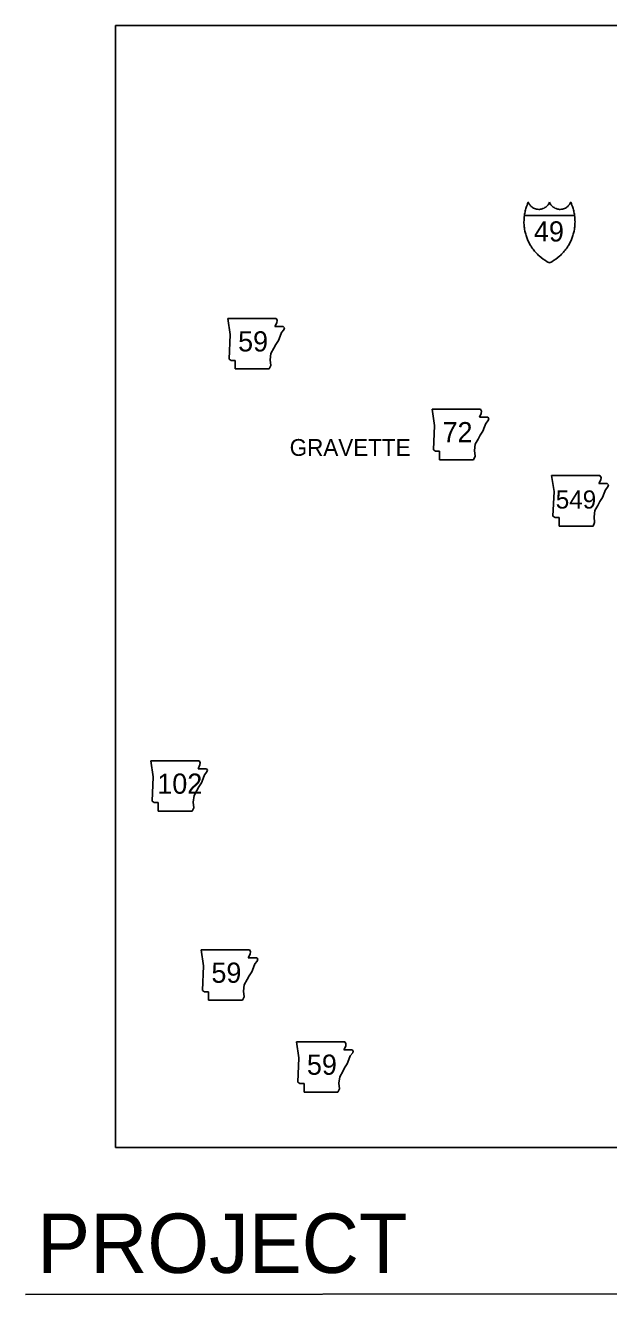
# Model space of a CAD drawing. Extents: x 6028647 to 6035072, y 5366486 to 5368495.
# Drawn here: x 6028660 to 6028935, y 5367847 to 5368445 of the extents above; entities that cross this region are included whole.
import ezdxf

# ---------------------------------------------------------------- set-up
doc = ezdxf.new("R2010")
doc.units = 0
for name, color, linetype in [('21', 7, 'Continuous'), ('22', 7, 'Continuous'), ('23', 7, 'Continuous'), ('25', 7, 'Continuous'), ('Default', 7, 'Continuous'), ('R_NoPlot', 7, 'Continuous')]:
    doc.layers.add(name, color=color, linetype=linetype)

msp = doc.modelspace()

# ---------------------------------------------------------------- linework, layer by layer
at = {"layer": '21'}
for p, q in [((6028755.11, 5368307.3), (6028756.25, 5368299.69)), ((6028777.44, 5368303.5), (6028778.33, 5368305.27)), ((6028778.45, 5368306.41), (6028777.93, 5368307.29)), ((6028778.33, 5368305.27), (6028778.45, 5368306.41)), ((6028756.25, 5368299.69), (6028755.74, 5368288.14)), ((6028781.37, 5368303.5), (6028777.44, 5368303.5)), ((6028779.85, 5368298.93), (6028780.48, 5368300.58)), ((6028780.48, 5368300.58), (6028781.63, 5368301.97)), ((6028781.88, 5368302.86), (6028781.37, 5368303.5)), ((6028781.63, 5368301.97), (6028781.88, 5368302.86)), ((6028775.54, 5368290.81), (6028776.93, 5368293.22)), ((6028776.93, 5368293.22), (6028777.82, 5368294.99)), ((6028777.82, 5368294.99), (6028779.09, 5368296.9)), ((6028779.09, 5368296.9), (6028779.85, 5368298.93)), ((6028755.74, 5368288.14), (6028756.76, 5368287.51)), ((6028756.76, 5368287.51), (6028758.66, 5368287.51)), ((6028758.66, 5368287.51), (6028758.66, 5368283.45)), ((6028775.16, 5368287.76), (6028775.54, 5368290.81)), ((6028775.41, 5368285.1), (6028775.16, 5368287.76)), ((6028758.66, 5368283.45), (6028774.65, 5368283.45)), ((6028774.65, 5368283.45), (6028775.41, 5368285.1)), ((6028851.55, 5368264.49), (6028852.69, 5368256.87)), ((6028874.9, 5368263.6), (6028874.37, 5368264.48)), ((6028874.77, 5368262.46), (6028874.9, 5368263.6)), ((6028873.88, 5368260.68), (6028874.77, 5368262.46)), ((6028877.82, 5368260.68), (6028873.88, 5368260.68)), ((6028876.29, 5368256.11), (6028876.93, 5368257.76)), ((6028876.93, 5368257.76), (6028878.07, 5368259.16)), ((6028878.32, 5368260.05), (6028877.82, 5368260.68)), ((6028878.07, 5368259.16), (6028878.32, 5368260.05)), ((6028852.69, 5368256.87), (6028852.18, 5368245.33)), ((6028873.37, 5368250.4), (6028874.26, 5368252.18)), ((6028874.26, 5368252.18), (6028875.53, 5368254.08)), ((6028875.53, 5368254.08), (6028876.29, 5368256.11)), ((6028852.18, 5368245.33), (6028853.2, 5368244.69)), ((6028871.6, 5368244.95), (6028871.98, 5368247.99)), ((6028871.98, 5368247.99), (6028873.37, 5368250.4)), ((6028853.2, 5368244.69), (6028855.1, 5368244.69)), ((6028855.1, 5368244.69), (6028855.1, 5368240.63)), ((6028855.1, 5368240.63), (6028871.09, 5368240.63)), ((6028871.09, 5368240.63), (6028871.85, 5368242.28)), ((6028871.85, 5368242.28), (6028871.6, 5368244.95)), ((6028907.98, 5368233.21), (6028909.13, 5368225.59)), ((6028930.32, 5368229.4), (6028931.2, 5368231.18)), ((6028934.25, 5368229.4), (6028930.32, 5368229.4)), ((6028931.33, 5368232.32), (6028930.8, 5368233.2)), ((6028931.2, 5368231.18), (6028931.33, 5368232.32)), ((6028933.36, 5368226.48), (6028934.5, 5368227.88)), ((6028934.76, 5368228.77), (6028934.25, 5368229.4)), ((6028934.5, 5368227.88), (6028934.76, 5368228.77)), ((6028909.13, 5368225.59), (6028908.62, 5368214.05)), ((6028930.7, 5368220.9), (6028931.96, 5368222.8)), ((6028931.96, 5368222.8), (6028932.73, 5368224.83)), ((6028932.73, 5368224.83), (6028933.36, 5368226.48)), ((6028928.03, 5368213.67), (6028928.41, 5368216.71)), ((6028928.41, 5368216.71), (6028929.81, 5368219.12)), ((6028929.81, 5368219.12), (6028930.7, 5368220.9)), ((6028908.62, 5368214.05), (6028909.63, 5368213.41)), ((6028909.63, 5368213.41), (6028911.54, 5368213.41)), ((6028911.54, 5368213.41), (6028911.54, 5368209.35)), ((6028911.54, 5368209.35), (6028927.52, 5368209.35)), ((6028927.52, 5368209.35), (6028928.29, 5368211)), ((6028928.29, 5368211), (6028928.03, 5368213.67)), ((6028718.8, 5368098.73), (6028719.94, 5368091.11)), ((6028741.13, 5368094.92), (6028742.01, 5368096.7)), ((6028742.14, 5368097.84), (6028741.62, 5368098.72)), ((6028742.01, 5368096.7), (6028742.14, 5368097.84)), ((6028719.94, 5368091.11), (6028719.43, 5368079.57)), ((6028745.06, 5368094.92), (6028741.13, 5368094.92)), ((6028742.78, 5368088.32), (6028743.54, 5368090.35)), ((6028743.54, 5368090.35), (6028744.17, 5368092)), ((6028744.17, 5368092), (6028745.31, 5368093.4)), ((6028745.57, 5368094.29), (6028745.06, 5368094.92)), ((6028745.31, 5368093.4), (6028745.57, 5368094.29)), ((6028739.22, 5368082.23), (6028740.62, 5368084.64)), ((6028740.62, 5368084.64), (6028741.51, 5368086.42)), ((6028741.51, 5368086.42), (6028742.78, 5368088.32)), ((6028719.43, 5368079.57), (6028720.44, 5368078.93)), ((6028720.44, 5368078.93), (6028722.35, 5368078.93)), ((6028722.35, 5368078.93), (6028722.35, 5368074.87)), ((6028738.84, 5368079.19), (6028739.22, 5368082.23)), ((6028739.1, 5368076.52), (6028738.84, 5368079.19)), ((6028722.35, 5368074.87), (6028738.34, 5368074.87)), ((6028738.34, 5368074.87), (6028739.1, 5368076.52)), ((6028742.52, 5368009.58), (6028743.66, 5368001.97)), ((6028764.85, 5368005.78), (6028765.74, 5368007.55)), ((6028765.87, 5368008.7), (6028765.34, 5368009.57)), ((6028765.74, 5368007.55), (6028765.87, 5368008.7)), ((6028743.66, 5368001.97), (6028743.16, 5367990.42)), ((6028768.79, 5368005.78), (6028764.85, 5368005.78)), ((6028766.5, 5367999.18), (6028767.26, 5368001.21)), ((6028767.26, 5368001.21), (6028767.9, 5368002.86)), ((6028767.9, 5368002.86), (6028769.04, 5368004.25)), ((6028769.29, 5368005.14), (6028768.79, 5368005.78)), ((6028769.04, 5368004.25), (6028769.29, 5368005.14)), ((6028762.95, 5367993.09), (6028764.35, 5367995.5)), ((6028764.35, 5367995.5), (6028765.23, 5367997.28)), ((6028765.23, 5367997.28), (6028766.5, 5367999.18)), ((6028743.16, 5367990.42), (6028744.17, 5367989.79)), ((6028744.17, 5367989.79), (6028746.07, 5367989.79)), ((6028746.07, 5367989.79), (6028746.07, 5367985.73)), ((6028762.57, 5367990.04), (6028762.95, 5367993.09)), ((6028762.82, 5367987.38), (6028762.57, 5367990.04)), ((6028746.07, 5367985.73), (6028762.06, 5367985.73)), ((6028762.06, 5367985.73), (6028762.82, 5367987.38)), ((6028787.58, 5367966.2), (6028788.72, 5367958.59)), ((6028809.91, 5367962.39), (6028810.8, 5367964.17)), ((6028810.93, 5367965.31), (6028810.4, 5367966.19)), ((6028810.8, 5367964.17), (6028810.93, 5367965.31)), ((6028788.72, 5367958.59), (6028788.21, 5367947.04)), ((6028813.84, 5367962.39), (6028809.91, 5367962.39)), ((6028812.32, 5367957.82), (6028812.96, 5367959.47)), ((6028812.96, 5367959.47), (6028814.1, 5367960.87)), ((6028814.35, 5367961.76), (6028813.84, 5367962.39)), ((6028814.1, 5367960.87), (6028814.35, 5367961.76)), ((6028808.01, 5367949.7), (6028809.4, 5367952.11)), ((6028809.4, 5367952.11), (6028810.29, 5367953.89)), ((6028810.29, 5367953.89), (6028811.56, 5367955.79)), ((6028811.56, 5367955.79), (6028812.32, 5367957.82)), ((6028788.21, 5367947.04), (6028789.23, 5367946.41)), ((6028789.23, 5367946.41), (6028791.13, 5367946.41)), ((6028791.13, 5367946.41), (6028791.13, 5367942.34)), ((6028807.63, 5367946.66), (6028808.01, 5367949.7)), ((6028807.88, 5367943.99), (6028807.63, 5367946.66)), ((6028791.13, 5367942.34), (6028807.12, 5367942.34)), ((6028807.12, 5367942.34), (6028807.88, 5367943.99))]:
    msp.add_line(p, q, dxfattribs=at)
for points in [[(6028755.11, 5368307.3), (6028777.93, 5368307.29)], [(6028851.55, 5368264.49), (6028874.37, 5368264.48)], [(6028907.98, 5368233.21), (6028930.8, 5368233.2)], [(6028718.8, 5368098.73), (6028741.62, 5368098.72)], [(6028742.52, 5368009.58), (6028765.34, 5368009.57)], [(6028787.58, 5367966.2), (6028810.4, 5367966.19)]]:
    msp.add_lwpolyline(points, dxfattribs=at)
at = {"layer": '23'}
for points in [[(6028895.15, 5368355.87), (6028895.24, 5368356.44), (6028895.33, 5368356.94), (6028895.46, 5368357.58), (6028895.55, 5368358), (6028895.68, 5368358.5), (6028895.85, 5368359.09), (6028896, 5368359.58), (6028896.17, 5368360.08), (6028896.39, 5368360.71), (6028896.62, 5368361.29), (6028896.82, 5368361.74), (6028896.98, 5368362.1), (6028897.15, 5368361.71), (6028897.35, 5368361.35), (6028897.57, 5368361.01), (6028897.86, 5368360.64), (6028898.09, 5368360.39), (6028898.37, 5368360.11), (6028898.66, 5368359.87), (6028898.96, 5368359.65), (6028899.45, 5368359.36), (6028899.96, 5368359.12), (6028900.41, 5368358.96), (6028900.86, 5368358.84), (6028901.35, 5368358.76), (6028901.91, 5368358.73), (6028902.28, 5368358.73), (6028902.7, 5368358.77), (6028903.08, 5368358.84), (6028903.48, 5368358.94), (6028903.89, 5368359.07), (6028904.44, 5368359.31), (6028904.81, 5368359.53), (6028905.25, 5368359.83), (6028905.67, 5368360.18), (6028905.98, 5368360.49), (6028906.33, 5368360.91), (6028906.62, 5368361.35), (6028906.79, 5368361.65), (6028906.98, 5368362.05)], [(6028895.15, 5368355.87), (6028895.24, 5368356.44), (6028895.33, 5368356.94), (6028895.46, 5368357.58), (6028895.55, 5368358), (6028895.68, 5368358.5), (6028895.85, 5368359.09), (6028896, 5368359.58), (6028896.17, 5368360.08), (6028896.39, 5368360.71), (6028896.62, 5368361.29), (6028896.82, 5368361.74), (6028896.98, 5368362.1), (6028897.15, 5368361.71), (6028897.35, 5368361.35), (6028897.57, 5368361.01), (6028897.86, 5368360.64), (6028898.09, 5368360.39), (6028898.37, 5368360.11), (6028898.66, 5368359.87), (6028898.96, 5368359.65), (6028899.45, 5368359.36), (6028899.96, 5368359.12), (6028900.41, 5368358.96), (6028900.86, 5368358.84), (6028901.35, 5368358.76), (6028901.91, 5368358.73), (6028902.28, 5368358.73), (6028902.7, 5368358.77), (6028903.08, 5368358.84), (6028903.48, 5368358.94), (6028903.89, 5368359.07), (6028904.44, 5368359.31), (6028904.81, 5368359.53), (6028905.25, 5368359.83), (6028905.67, 5368360.18), (6028905.98, 5368360.49), (6028906.33, 5368360.91), (6028906.62, 5368361.35), (6028906.79, 5368361.65), (6028906.98, 5368362.05)], [(6028906.98, 5368362.05), (6028907.16, 5368361.65), (6028907.33, 5368361.35), (6028907.62, 5368360.91), (6028907.97, 5368360.49), (6028908.28, 5368360.18), (6028908.7, 5368359.83), (6028909.14, 5368359.53), (6028909.52, 5368359.31), (6028910.06, 5368359.07), (6028910.47, 5368358.94), (6028910.87, 5368358.84), (6028911.25, 5368358.77), (6028911.68, 5368358.73), (6028912.04, 5368358.73), (6028912.61, 5368358.76), (6028913.09, 5368358.84), (6028913.54, 5368358.96), (6028914, 5368359.12), (6028914.5, 5368359.36), (6028914.99, 5368359.65), (6028915.3, 5368359.87), (6028915.58, 5368360.11), (6028915.86, 5368360.39), (6028916.09, 5368360.64), (6028916.38, 5368361.01), (6028916.6, 5368361.35), (6028916.8, 5368361.71), (6028916.98, 5368362.1), (6028917.14, 5368361.74), (6028917.33, 5368361.29), (6028917.56, 5368360.71), (6028917.79, 5368360.08), (6028917.96, 5368359.58), (6028918.11, 5368359.09), (6028918.27, 5368358.5), (6028918.4, 5368358), (6028918.5, 5368357.58), (6028918.63, 5368356.94), (6028918.72, 5368356.44), (6028918.8, 5368355.87)], [(6028906.98, 5368362.05), (6028907.16, 5368361.65), (6028907.33, 5368361.35), (6028907.62, 5368360.91), (6028907.97, 5368360.49), (6028908.28, 5368360.18), (6028908.7, 5368359.83), (6028909.14, 5368359.53), (6028909.52, 5368359.31), (6028910.06, 5368359.07), (6028910.47, 5368358.94), (6028910.87, 5368358.84), (6028911.25, 5368358.77), (6028911.68, 5368358.73), (6028912.04, 5368358.73), (6028912.61, 5368358.76), (6028913.09, 5368358.84), (6028913.54, 5368358.96), (6028914, 5368359.12), (6028914.5, 5368359.36), (6028914.99, 5368359.65), (6028915.3, 5368359.87), (6028915.58, 5368360.11), (6028915.86, 5368360.39), (6028916.09, 5368360.64), (6028916.38, 5368361.01), (6028916.6, 5368361.35), (6028916.8, 5368361.71), (6028916.98, 5368362.1), (6028917.14, 5368361.74), (6028917.33, 5368361.29), (6028917.56, 5368360.71), (6028917.79, 5368360.08), (6028917.96, 5368359.58), (6028918.11, 5368359.09), (6028918.27, 5368358.5), (6028918.4, 5368358), (6028918.5, 5368357.58), (6028918.63, 5368356.94), (6028918.72, 5368356.44), (6028918.8, 5368355.87)], [(6028906.98, 5368333.47), (6028905.94, 5368334.02), (6028905.03, 5368334.57), (6028904.03, 5368335.25), (6028903.09, 5368335.96), (6028902.07, 5368336.83), (6028901.68, 5368337.18), (6028901.25, 5368337.61), (6028900.85, 5368338.02), (6028900.41, 5368338.51), (6028899.97, 5368339.01), (6028899.61, 5368339.46), (6028899.22, 5368339.97), (6028898.87, 5368340.46), (6028898.56, 5368340.91), (6028898.29, 5368341.33), (6028898.06, 5368341.69), (6028897.77, 5368342.19), (6028897.54, 5368342.61), (6028897.28, 5368343.09), (6028897.04, 5368343.59), (6028896.82, 5368344.05), (6028896.63, 5368344.5), (6028896.42, 5368345), (6028896.25, 5368345.46), (6028896.08, 5368345.95), (6028895.91, 5368346.46), (6028895.76, 5368346.97), (6028895.62, 5368347.47), (6028895.5, 5368347.94), (6028895.41, 5368348.36), (6028895.34, 5368348.67), (6028895.23, 5368349.27), (6028895.12, 5368349.97), (6028895.05, 5368350.54), (6028895, 5368351.16), (6028894.96, 5368351.65), (6028894.94, 5368352.28), (6028894.93, 5368352.86), (6028894.95, 5368353.51), (6028894.96, 5368353.94), (6028894.99, 5368354.33), (6028895.01, 5368354.58), (6028895.07, 5368355.22), (6028895.15, 5368355.87)], [(6028918.8, 5368355.87), (6028895.15, 5368355.87)], [(6028918.8, 5368355.87), (6028895.15, 5368355.87)], [(6028918.8, 5368355.87), (6028918.89, 5368355.22), (6028918.95, 5368354.58), (6028918.97, 5368354.33), (6028918.99, 5368353.94), (6028919.01, 5368353.51), (6028919.02, 5368352.86), (6028919.01, 5368352.28), (6028918.99, 5368351.65), (6028918.96, 5368351.16), (6028918.91, 5368350.54), (6028918.83, 5368349.97), (6028918.72, 5368349.27), (6028918.61, 5368348.67), (6028918.55, 5368348.36), (6028918.45, 5368347.94), (6028918.33, 5368347.47), (6028918.2, 5368346.97), (6028918.04, 5368346.46), (6028917.88, 5368345.95), (6028917.71, 5368345.46), (6028917.53, 5368345), (6028917.33, 5368344.5), (6028917.13, 5368344.05), (6028916.92, 5368343.59), (6028916.67, 5368343.09), (6028916.42, 5368342.61), (6028916.19, 5368342.19), (6028915.89, 5368341.69), (6028915.67, 5368341.33), (6028915.4, 5368340.91), (6028915.09, 5368340.46), (6028914.73, 5368339.97), (6028914.34, 5368339.46), (6028913.98, 5368339.01), (6028913.55, 5368338.51), (6028913.11, 5368338.02), (6028912.7, 5368337.61), (6028912.27, 5368337.18), (6028911.89, 5368336.83), (6028910.86, 5368335.96), (6028909.93, 5368335.25), (6028908.93, 5368334.57), (6028908.01, 5368334.02), (6028906.98, 5368333.47)]]:
    msp.add_lwpolyline(points, dxfattribs=at)
at = {"layer": 'Default'}
msp.add_lwpolyline([(6028985.94, 5368220.75), (6028940.2, 5367847.26), (6028659.63, 5367846.93)], dxfattribs=at)
at = {"layer": 'R_NoPlot'}
msp.add_lwpolyline([(6028702.18, 5368445.48), (6029287.88, 5368445.48), (6029287.88, 5367916.32), (6028702.18, 5367916.32)], close=True, dxfattribs=at)

# ---------------------------------------------------------------- texts
at = {"layer": '21'}
for s, height, p in [('59', 9.504, (6028760.03, 5368291.71)), ('72', 9.504, (6028856.51, 5368248.9)), ('549', 8.554, (6028909.93, 5368217.62)), ('102', 9.504, (6028721.91, 5368083.14)), ('59', 9.504, (6028747.44, 5367993.99)), ('59', 9.504, (6028792.5, 5367950.61))]:
    msp.add_text(s, height=height, dxfattribs=at).set_placement(p)
at = {"layer": '22'}
msp.add_text('49', height=9.504, dxfattribs=at).set_placement((6028899.65, 5368343.58))
at = {"layer": '25'}
msp.add_text('GRAVETTE', height=7.92, dxfattribs=at).set_placement((6028784.36, 5368242.48))
at = {"layer": 'Default'}
msp.add_text('PROJECT', height=28, dxfattribs=at).set_placement((6028665.2, 5367857.15))

doc.saveas('drawing.dxf')
